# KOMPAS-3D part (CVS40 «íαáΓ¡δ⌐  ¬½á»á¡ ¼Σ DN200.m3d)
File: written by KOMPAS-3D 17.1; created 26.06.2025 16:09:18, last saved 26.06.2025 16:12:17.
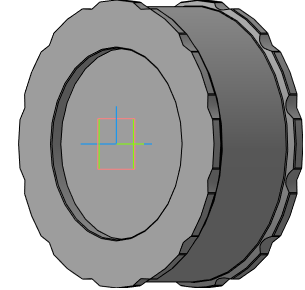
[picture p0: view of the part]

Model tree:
1. Эскиз:1
2. Элемент вращения:1
     Угол 1 = 360
3. Эскиз:2
4. Элемент выдавливания:1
